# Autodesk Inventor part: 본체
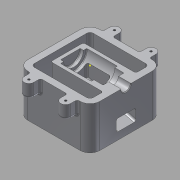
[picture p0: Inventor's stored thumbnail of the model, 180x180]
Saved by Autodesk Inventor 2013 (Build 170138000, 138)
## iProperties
Created: 2018-01
Part Number: 본체
Material: 알루미늄 6061
Document SubType Name: Modeling
Designer: Administrator
Density: 2.71 g/cm^3
Mass: 995.766 g
Surface Area: 840.611 cm^2
Volume: 367.441 cm^3
Author: Administrator
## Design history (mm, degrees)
sketch "스케치1"
  geometry: L1 (-55, 55)-(55, 55); L2 (55, 55)-(55, -55); L3 (55, -55)-(-55, -55); L4 (-55, -55)-(-55, 55); 3 further points
  constraints: 8 end point, 2 midpoint, 2 parallel, 1 horizontal, 1 horizontal alignment, 1 perpendicular, 1 vertical alignment
  dimensions: "d0" = 110 distance of L1.start L1.end; "d2" = 110 distance of L3.end L1.start
extrude "돌출1" new body sketch "스케치1" distance "d3" = 65; taper "d4" = 0 deg
sketch "스케치4"
  geometry: L1 (-55, 55)-(55, 55) reference; L2 (-20.5, 65.186)-(-20.5, 55); L3 (-35.5, 55)-(-35.5, 65.186); L4 (-35.5, 55)-(-20.5, 55); A1 r 7.5 centre (-28, 65.186) between (-20.5, 65.186) and (-35.5, 65.186); 1 further point
  constraints: 6 end point, 2 point on circle, 2 tangent, 1 centre point, 1 parallel, 1 point on line
  dimensions: "d11" = 15 diameter of A1; "d14" = 27 horizontal distance of L1.start A1.centre
extrude "돌출3" join sketch "스케치4" distance "d21" = 20; taper "d22" = 0 deg
sketch "스케치5"
  geometry: A1 r 7.5 centre (-28, -65.186) between (-35.5, -65.186) and (-20.5, -65.186) reference; A2 r 7.5 centre (28, -65.186) between (20.5, -65.186) and (35.5, -65.186) reference; A3 r 7.5 centre (28, 65.186) between (35.5, 65.186) and (20.5, 65.186) reference; A4 r 7.5 centre (-28, 65.186) between (-20.5, 65.186) and (-35.5, 65.186) reference; 5 further points
  constraints: 4 coincident
hole "구멍1" sketch "스케치5" at (-28, 65.186), (28, 65.186), (-28, -65.186), (28, -65.186) diameter "d26" = 3.242; stored, may be unused: countersink angle "d30" = 90 deg, drill point angle "d32" = 118 deg; dims "d27" = 9, "d28" = 4, "d29" = 2, "d31" = 11
sketch "스케치9"
  geometry: 1 further point
sketch "스케치10"
  geometry: L1 (-55, -65)-(-55, 0) reference; L2 (-55, 0)-(55, 0) reference; L3 (55, 0)-(55, -65) reference; L4 (55, -65)-(-55, -65) reference; L5 (-45, -65)-(-45, -56.436); L6 (-45, -56.436)-(35, -35); L7 (35, -35)-(35, 0); L8 (45, 0)-(45, -65); 1 further point
  constraints: 8 end point, 4 point on line, 2 perpendicular, 1 parallel
  dimensions: "d56" = 10 distance between parallel lines of L1 L5; "d57" = 105 deg angle of L6 L5; "d58" = 30 distance from line of L4 L6.end; "d59" = 10 distance between parallel lines of L8 L7; "d60" = 10 distance between parallel lines of L3 L8
extrude "돌출5" cut sketch "스케치10" stored distance "d61" = 90; taper "d62" = 0 deg
sketch "스케치11"
  geometry: L1 (55, 0)-(55, -65) reference; L2 (55, -65)-(45, -65) reference; L3 (45, -65)-(45, 0) reference; L4 (45, 0)-(55, 0) reference; L5 (-55, -65)-(-55, 0) reference; L6 (-55, 0)-(35, 0) reference; L7 (35, 0)-(35, -35) reference; L8 (35, -35)-(-45, -56.436) reference; L9 (-45, -56.436)-(-45, -65) reference; L10 (-45, -65)-(-55, -65) reference; L11 (-55, -7.5)-(-36, -7.5); L12 (-36, -7.5)-(-36, -16); L13 (-36, -16)-(-22, -16); L14 (-22, -16)-(-22, -20); L15 (-22, -20)-(25, -20); L16 (25, -20)-(25, -15); L17 (25, -15)-(30, -15); L18 (30, -15)-(30, 0); 1 further point
  constraints: 16 end point, 5 parallel, 3 perpendicular, 2 point on line
  dimensions: "d63" = 15 diameter of L11 L6; "d64" = 32 diameter of L13 L6; "d65" = 40 diameter of L15 L6; "d66" = 30 diameter of L17 L6; "d67" = 19 distance of L11.start L11.end; "d68" = 14 distance of L12.end L13.end; "d69" = 47 distance of L14.end L15.end; "d70" = 5 distance of L16.end L17.end
revolve "회전1" sketch "스케치11" stored, may be unused: angle "d71" = 90 deg
sketch "스케치13"
  geometry: L1 (-55, -35.939)-(-17, -25.757); L2 (45, 0)-(55, 0) reference; L3 (55, 0)-(55, -65) reference; L4 (55, -65)-(45, -65) reference; L5 (45, -65)-(45, 0) reference; L6 (-45, -56.436)-(-45, -65) reference; L7 (-45, -65)-(-55, -65) reference; L8 (-55, -65)-(-55, -7.5) reference; L9 (-55, -7.5)-(-36, -7.5) reference; L10 (-36, -7.5)-(-36, -16) reference; L11 (-36, -16)-(-22, -16) reference; L12 (-22, -16)-(-22, -20) reference; L13 (-22, -20)-(25, -20) reference; L14 (25, -20)-(25, -15) reference; L15 (25, -15)-(30, -15) reference; L16 (30, -15)-(30, 0) reference; L17 (30, 0)-(35, 0) reference; L18 (35, 0)-(35, -35) reference; L19 (35, -35)-(-45, -56.436) reference; L20 (20, -33.843)-(-55, -53.939); L21 (20, -33.843)-(20, -13.281); L22 (20, -13.281)-(-17, -13.281); L23 (-17, -13.281)-(-17, -25.757); L24 (-22, 0)-(-22, -16) reference; 1 further point
  constraints: 10 end point, 5 parallel, 2 point on line
  dimensions: "d77" = 18 distance of L20.end L1.start; "d121" = 5 distance between parallel lines of L19 L20; "d122" = 37 distance of L21.end L22.end; "d125" = 20.56234 distance of L20.start L21.end; "d126" = 5 distance from line of L22.end L24
extrude "돌출6" cut sketch "스케치13" stored distance "d80" = 30; taper "d81" = 0 deg
sketch "스케치14"
  geometry: L1 (55, -7.5)-(36, -7.5) reference; L2 (36, -7.5)-(36, -16) reference; L3 (-20.5, 55)-(20.5, 55) reference; L4 (20.5, -55)-(-20.5, -55) reference; L5 (-35, 45)-(-35, -45) reference; L6 (45, -25)-(-35, -25); L7 (45, 25)-(-35, 25); L8 (45, 45)-(-35, 45); L9 (45, -45)-(-35, -45); L10 (-35, -44.481)-(-35, -25); L11 (-35, 25)-(-35, 45); L12 (45, -45)-(45, -25); L13 (55, -7.5)-(55, -55) reference; L14 (45, 25)-(45, 45); L15 (55, 55)-(55, 7.5) reference; 1 further point
  constraints: 16 end point, 5 point on line, 4 parallel, 2 perpendicular
  dimensions: "d82" = 50 distance between parallel lines of L7 L6; "d83" = 25 distance from line of L6 point (0, 0); "d85" = 10 distance between parallel lines of L3 L8; "d86" = 10 distance between parallel lines of L4 L9; "d87" = 10 distance between parallel lines of L13 L12; "d88" = 10 distance between parallel lines of L15 L14
extrude "돌출7" cut sketch "스케치14" distance "d89" = 124.75; taper "d90" = 0 deg
fillet "모깎기2" dims "d93" = 3
fillet "모깎기3" dims "d94" = 3
chamfer "모따기1" distance "d95" = 1; stored, may be unused: second distance "d96" = 2, angle "d97" = 45 deg
fillet "모깎기5" dims "d99" = 1
fillet "모깎기8" dims "d127" = 3
fillet "모깎기9" dims "d128" = 15
fillet "모깎기12" dims "d131" = 3
fillet "모깎기13" dims "d132" = 3
node "작업 평면1"
sketch "스케치19" dims "d0" = 110, "d2" = 110
  geometry: L1 (72.5, 0)-(72.5, 65) reference; L2 (57.5, 65)-(72.5, 65) reference; 2 further points
  constraints: 1 other
  dimensions: "d136" = 55 distance from line of L1 point (17.5, 45); "d137" = 20 distance from line of L2 point (17.5, 45)
feature "엠보싱1" sketch "스케치19" dims "d0" = 110, "d2" = 110, "d138" = 0.5, "d139" = 0
fillet "모깎기14" dims "d140" = 5
node "솔리드1"
pattern_linear "직사각형 패턴1" dims "d25" = 56
mirror "대칭1"
node "절단 모서리 투영3"
node "절단 모서리 투영4"
node "절단 모서리 투영5"
other parameters: "d135" = 123
